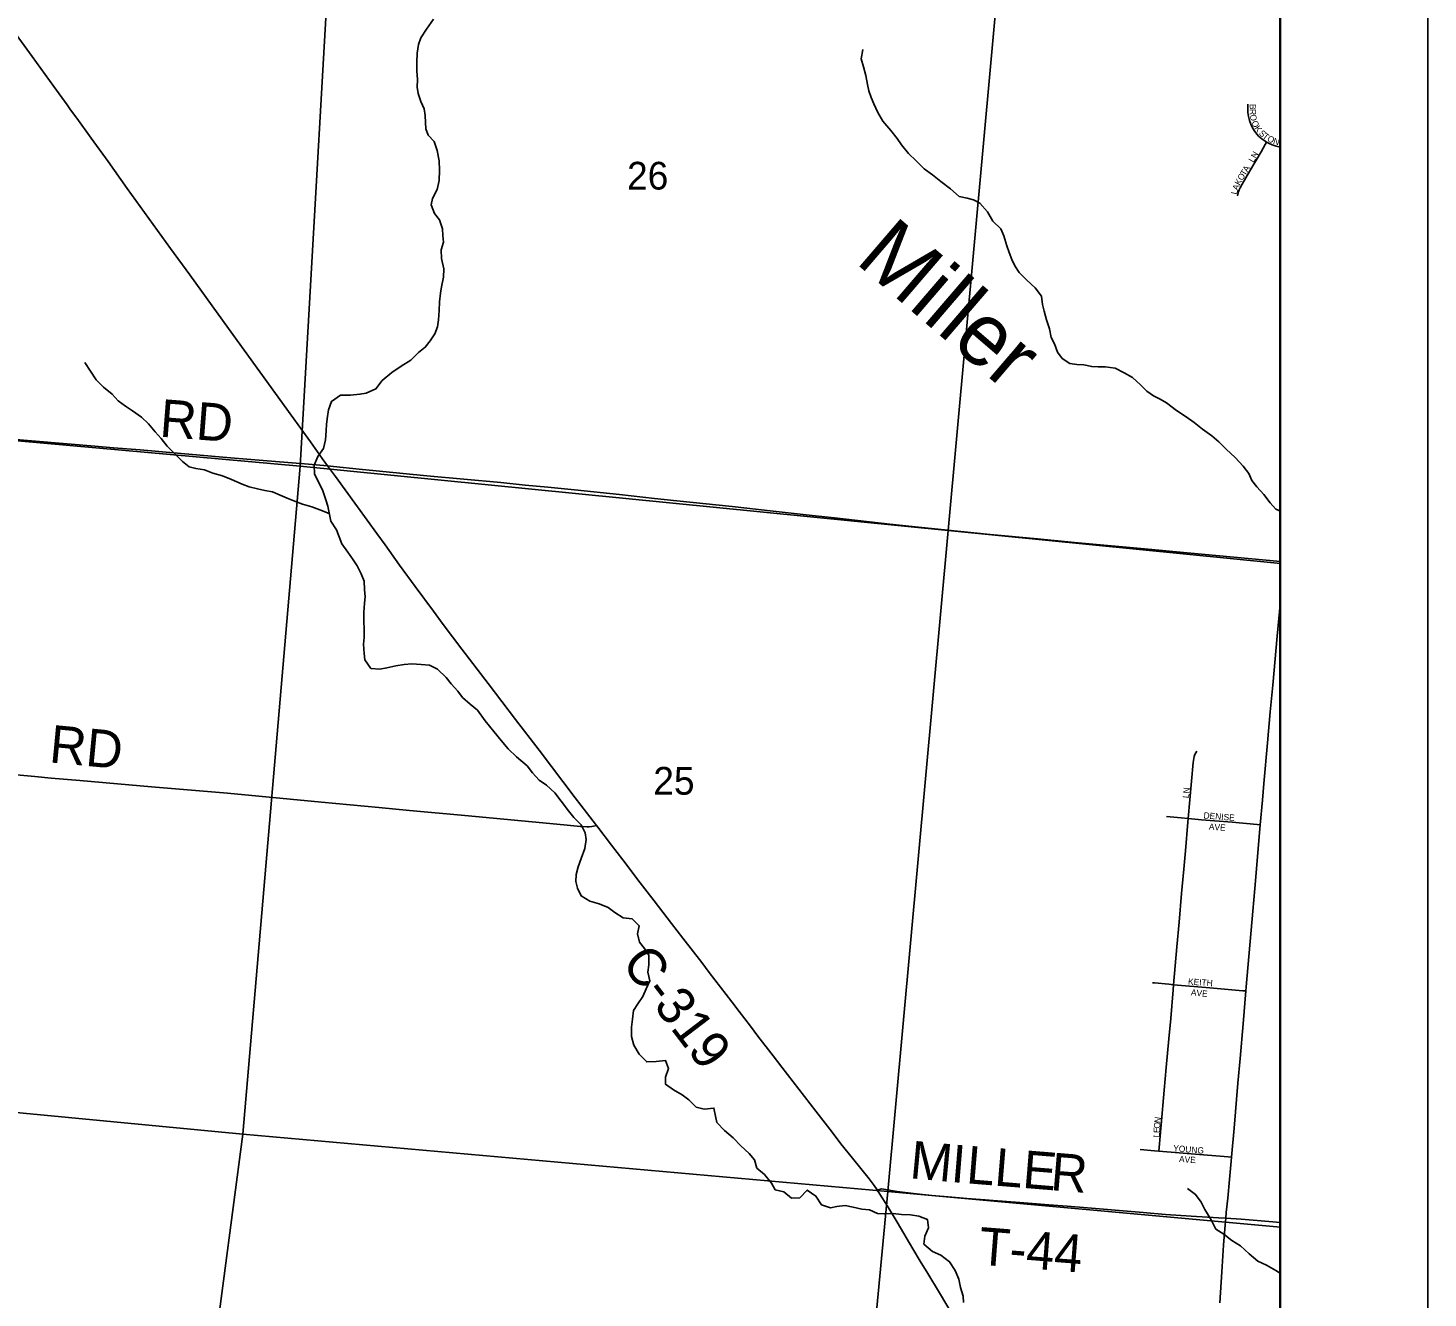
# Model space of a CAD drawing. Extents: x 0 to 680, y 0 to 440.
# Drawn here: x 255.45 to 288.52, y 350.9 to 380.9 of the extents above; entities that cross this region are included whole.
import ezdxf

# ---------------------------------------------------------------- set-up
doc = ezdxf.new("R2010")
doc.units = 0
for name, color, linetype in [('GM_X_Adjacent_County', 7, 'Continuous'), ('GM_X_County', 7, 'Continuous'), ('GM_X_County_Road', 7, 'Continuous'), ('GM_X_County_Road_Text', 7, 'Continuous'), ('GM_X_Minor_River', 7, 'Continuous'), ('GM_X_Minor_River_Text', 7, 'Continuous'), ('GM_X_Section', 7, 'Continuous'), ('GM_X_Section_Text', 7, 'Continuous'), ('GM_X_Township', 7, 'Continuous'), ('GM_X_Township_Road', 7, 'Continuous'), ('GM_X_Township_Road_Text', 7, 'Continuous'), ('GM_X_Township_Subdivision', 7, 'Continuous'), ('GM_X_Township_Subdivision_Text', 7, 'Continuous'), ('SH_Data', 7, 'Continuous'), ('SH_Text', 7, 'Continuous')]:
    doc.layers.add(name, color=color, linetype=linetype)

msp = doc.modelspace()

# ---------------------------------------------------------------- linework, layer by layer
at = {"layer": 'GM_X_Adjacent_County'}
msp.add_lwpolyline([(285.035, 209.752), (285.035, 415.359), (154.698, 415.359)], dxfattribs=at)
at = {"layer": 'GM_X_County'}
msp.add_lwpolyline([(285.035, 209.752), (285.035, 415.359), (154.698, 415.359)], dxfattribs=at)
at = {"layer": 'GM_X_County_Road'}
for points in [[(256.452, 378.972), (256.371, 379.085), (256.058, 379.518), (255.545, 380.227), (254.835, 381.212), (254.38, 381.844), (253.671, 382.83), (253.129, 383.576), (252.618, 384.286), (251.562, 385.742), (251.165, 386.286), (250.907, 386.649), (250.671, 386.958), (250.531, 387.144), (250.516, 387.171), (250.506, 387.2), (250.496, 387.255)], [(262.525, 370.561), (262.402, 370.727), (262.12, 371.123), (261.667, 371.758), (260.925, 372.779), (260.187, 373.805), (259.269, 375.073), (258.818, 375.695), (257.791, 377.113), (257.34, 377.746), (256.94, 378.297), (256.599, 378.77), (256.452, 378.972)], [(268.878, 362.058), (268.642, 362.366), (268.378, 362.715), (267.522, 363.836), (266.965, 364.565), (266.64, 364.99), (266.316, 365.415), (265.7, 366.229), (265.259, 366.809), (265.026, 367.121), (264.592, 367.706), (264.228, 368.212), (263.884, 368.693), (263.689, 368.962), (263.229, 369.589), (262.714, 370.307), (262.525, 370.561)], [(275.505, 353.451), (275.436, 353.552), (275.319, 353.708), (274.922, 354.2), (274.65, 354.542), (274.442, 354.811), (274.057, 355.312), (273.79, 355.659), (273.257, 356.351), (273.048, 356.62), (272.693, 357.083), (272.517, 357.315), (272.252, 357.663), (272.075, 357.894), (271.542, 358.589), (271.365, 358.82), (270.92, 359.397), (270.654, 359.745), (270.238, 360.283), (269.913, 360.708), (269.498, 361.247), (269.234, 361.595), (268.908, 362.019), (268.878, 362.058)], [(280.496, 345.113), (280.311, 345.424), (280.086, 345.799), (279.856, 346.184), (279.636, 346.549), (279.485, 346.799), (278.96, 347.674), (278.787, 347.967), (278.44, 348.552), (278.29, 348.802), (278.019, 349.263), (277.896, 349.472), (277.671, 349.848), (277.302, 350.476), (276.98, 351.021), (276.702, 351.477), (276.527, 351.769), (276.352, 352.061), (275.981, 352.688), (275.754, 353.063), (275.573, 353.351), (275.505, 353.451)]]:
    msp.add_lwpolyline(points, dxfattribs=at)
at = {"layer": 'GM_X_Minor_River'}
for points in [[(263.117, 368.359), (263.006, 368.515), (262.866, 368.712), (262.739, 369.047), (262.605, 369.25), (262.56, 369.447), (262.532, 369.602), (262.486, 369.751), (262.412, 369.966), (262.215, 370.372), (262.211, 370.574), (262.297, 370.775), (262.43, 370.964), (262.474, 371.171), (262.489, 371.385), (262.502, 371.539), (262.523, 371.723), (262.548, 371.878), (262.616, 372.079), (262.832, 372.225), (263.07, 372.228), (263.29, 372.249), (263.439, 372.277), (263.666, 372.376), (263.817, 372.57), (264.046, 372.763), (264.261, 372.91), (264.489, 373.055), (264.67, 373.232), (264.832, 373.36), (264.947, 373.514), (265.062, 373.673), (265.123, 373.838), (265.143, 374.011), (265.158, 374.23), (265.166, 374.432), (265.192, 374.634), (265.218, 374.788), (265.262, 375.014), (265.271, 375.21), (265.214, 375.454), (265.211, 375.662), (265.261, 375.84), (265.251, 376), (265.241, 376.155), (265.166, 376.37), (265.049, 376.52), (264.974, 376.723), (265.006, 376.871), (265.115, 377.083), (265.16, 377.303), (265.169, 377.546), (265.159, 377.766), (265.115, 378.01), (265.046, 378.219), (264.899, 378.37), (264.848, 378.519), (264.838, 378.673), (264.834, 378.834), (264.806, 378.989), (264.731, 379.168), (264.668, 379.353), (264.646, 379.502), (264.648, 379.686), (264.638, 379.894), (264.635, 380.096), (264.643, 380.304), (264.676, 380.512), (264.725, 380.666), (264.859, 380.878), (265.028, 381.108)], [(275.278, 379.568), (275.239, 379.782), (275.182, 379.985), (275.13, 380.17), (275.169, 380.395)], [(285.035, 369.487), (284.924, 369.53), (284.795, 369.68), (284.642, 369.884), (284.478, 370.059), (284.361, 370.208), (284.286, 370.376), (284.157, 370.55), (283.969, 370.754), (283.752, 370.953), (283.582, 371.127), (283.417, 371.265), (283.193, 371.423), (282.998, 371.579), (282.804, 371.712), (282.58, 371.864), (282.344, 372.045), (282.191, 372.136), (282.037, 372.209), (281.878, 372.318), (281.725, 372.474), (281.543, 372.648), (281.342, 372.758), (281.129, 372.867), (280.898, 372.899), (280.731, 372.895), (280.577, 372.903), (280.387, 372.947), (280.221, 372.955), (280.06, 372.975), (279.878, 373.096), (279.766, 373.246), (279.697, 373.437), (279.622, 373.586), (279.577, 373.795), (279.508, 374.009), (279.451, 374.212), (279.412, 374.373), (279.39, 374.563), (279.244, 374.761), (279.044, 374.948), (278.862, 375.122), (278.763, 375.284), (278.687, 375.433), (278.624, 375.6), (278.572, 375.756), (278.504, 375.994), (278.429, 376.155), (278.241, 376.336), (278.118, 376.557), (277.937, 376.767), (277.783, 376.846), (277.635, 376.878), (277.445, 376.922), (277.239, 377.102), (277.015, 377.277), (276.815, 377.434), (276.621, 377.573), (276.427, 377.76), (276.245, 377.94), (276.087, 378.138), (275.981, 378.288), (275.829, 378.48), (275.642, 378.702), (275.525, 378.905), (275.427, 379.114), (275.369, 379.264), (275.311, 379.419), (275.278, 379.568)], [(262.564, 369.431), (262.341, 369.521), (262.151, 369.588), (261.932, 369.65), (261.767, 369.712), (261.571, 369.791), (261.406, 369.864), (261.228, 369.944), (261.044, 369.976), (260.872, 370.013), (260.671, 370.063), (260.511, 370.125), (260.257, 370.235), (260.044, 370.32), (259.819, 370.388), (259.617, 370.462), (259.416, 370.494), (259.256, 370.537), (259.097, 370.658), (258.938, 370.821), (258.738, 371.019), (258.592, 371.205), (258.457, 371.361), (258.299, 371.553), (258.128, 371.71), (257.916, 371.861), (257.751, 371.97), (257.58, 372.096), (257.439, 372.253), (257.233, 372.415), (257.057, 372.59), (256.789, 372.997)], [(273.682, 353.263), (273.485, 353.254), (273.303, 353.404), (273.101, 353.448), (273.014, 353.61), (272.85, 353.814), (272.668, 353.965), (272.611, 354.161), (272.482, 354.312), (272.288, 354.492), (272.106, 354.684), (271.9, 354.853), (271.724, 355.04), (271.69, 355.189), (271.651, 355.385), (271.424, 355.358), (271.235, 355.402), (271.058, 355.576), (270.899, 355.697), (270.699, 355.812), (270.51, 355.945), (270.506, 356.112), (270.58, 356.319), (270.505, 356.51), (270.285, 356.483), (270.065, 356.474), (269.889, 356.654), (269.76, 356.87), (269.704, 357.078), (269.706, 357.292), (269.732, 357.488), (269.753, 357.69), (269.856, 357.843), (269.971, 358.02), (270.05, 358.204), (270.136, 358.393), (270.091, 358.595), (270.117, 358.768), (270.114, 358.999), (270.015, 359.155), (269.897, 359.305), (269.846, 359.502), (269.89, 359.691), (269.72, 359.854), (269.512, 359.88), (269.311, 360.007), (269.152, 360.122), (268.939, 360.208), (268.72, 360.27), (268.52, 360.397), (268.427, 360.576), (268.393, 360.737), (268.395, 360.904), (268.445, 361.081), (268.513, 361.277), (268.599, 361.513), (268.637, 361.727), (268.609, 361.888), (268.516, 362.073), (268.346, 362.247), (268.217, 362.403), (268.042, 362.631), (267.895, 362.835), (267.695, 363.01), (267.524, 363.131), (267.366, 363.305), (267.237, 363.473), (266.99, 363.684), (266.79, 363.87), (266.626, 364.068), (266.451, 364.278), (266.246, 364.536), (266.064, 364.782), (265.894, 364.927), (265.717, 365.083), (265.6, 365.233), (265.442, 365.407), (265.331, 365.557), (265.125, 365.756), (264.93, 365.847), (264.734, 365.867), (264.52, 365.876), (264.335, 365.86), (264.139, 365.833), (263.924, 365.782), (263.757, 365.754), (263.549, 365.768), (263.409, 365.972), (263.393, 366.121), (263.378, 366.347), (263.392, 366.501), (263.389, 366.709), (263.379, 366.876), (263.381, 367.096), (263.402, 367.309), (263.41, 367.464), (263.4, 367.636), (263.39, 367.832), (263.321, 368.006), (263.222, 368.197), (263.117, 368.359)], [(277.546, 350.793), (277.542, 350.941), (277.479, 351.144), (277.434, 351.341), (277.347, 351.544), (277.219, 351.754), (277.013, 351.905), (276.812, 351.996), (276.612, 352.171), (276.632, 352.355), (276.723, 352.556), (276.696, 352.752), (276.495, 352.826), (276.293, 352.858), (276.085, 352.867), (275.889, 352.893), (275.675, 352.883), (275.52, 352.891), (275.325, 352.982), (275.147, 352.996), (274.94, 353.046), (274.756, 353.078), (274.559, 353.057), (274.404, 353.029), (274.197, 353.097), (274.063, 353.306), (273.857, 353.445), (273.682, 353.263)], [(285.035, 351.477), (284.922, 351.545), (284.704, 351.672), (284.503, 351.77), (284.297, 351.938), (284.091, 352.125), (283.89, 352.252), (283.696, 352.403), (283.507, 352.524), (283.397, 352.74), (283.251, 352.985), (283.158, 353.164), (283.03, 353.344), (282.841, 353.483)]]:
    msp.add_lwpolyline(points, dxfattribs=at)
at = {"layer": 'GM_X_Section'}
for points in [[(248.075, 387.46), (262.767, 386.107), (261.88, 370.548), (246.691, 371.915)], [(262.767, 386.107), (278.599, 384.575), (277.185, 369.031), (261.88, 370.548)], [(285.035, 368.251), (285.035, 383.915), (278.599, 384.575), (277.185, 369.031)], [(246.691, 371.915), (261.88, 370.548), (260.527, 354.766), (245.115, 356.243)], [(261.88, 370.548), (277.185, 369.031), (275.758, 353.416), (260.527, 354.766)], [(285.035, 352.57), (285.035, 368.251), (277.185, 369.031), (275.758, 353.416)], [(245.115, 356.243), (260.527, 354.766), (258.466, 339.173), (243.775, 340.544)], [(260.527, 354.766), (275.758, 353.416), (274.289, 337.825), (258.466, 339.173)], [(285.035, 336.872), (285.035, 352.57), (275.758, 353.416), (274.289, 337.825)]]:
    msp.add_lwpolyline(points, close=True, dxfattribs=at)
at = {"layer": 'GM_X_Township'}
msp.add_lwpolyline([(243.787, 340.531), (258.485, 339.173), (267.813, 338.347), (274.304, 337.773), (285.035, 336.894), (285.035, 415.359)], dxfattribs=at)
at = {"layer": 'GM_X_Township_Road'}
for points in [[(246.687, 371.891), (246.791, 371.883), (246.888, 371.875), (247.422, 371.828), (248.004, 371.785), (250.819, 371.549), (251.353, 371.505), (252.372, 371.42), (252.905, 371.372), (253.536, 371.318), (254.215, 371.259), (257.029, 371.021), (257.466, 370.984), (258.096, 370.932), (259.067, 370.847), (260.231, 370.748), (261.008, 370.685), (262.075, 370.596), (262.525, 370.561)], [(262.525, 370.561), (262.667, 370.541), (263.273, 370.479), (264.871, 370.325), (266.615, 370.16), (267.196, 370.103), (267.728, 370.051), (268.358, 369.987), (269.423, 369.877), (270.245, 369.785), (270.777, 369.728), (272.084, 369.594), (273.051, 369.484), (273.97, 369.386), (274.502, 369.326), (275.808, 369.179), (276.485, 369.109), (278.18, 368.935), (279.294, 368.831), (280.166, 368.749), (281.91, 368.586), (282.829, 368.505), (285.035, 368.299)], [(284.558, 362.077), (284.609, 362.659), (284.643, 363.05), (284.731, 364.016), (284.795, 364.743), (284.854, 365.372), (284.96, 366.535), (285.035, 367.365)], [(254.641, 363.306), (255.609, 363.219), (255.996, 363.182), (256.673, 363.125), (257.835, 363.024), (258.367, 362.975), (260.158, 362.821), (262.383, 362.609), (263.738, 362.482), (264.463, 362.413), (265.77, 362.295), (267.362, 362.145), (268.104, 362.072), (268.502, 362.037), (268.505, 362.037)], [(268.505, 362.037), (268.647, 362.027), (268.704, 362.027), (268.769, 362.037), (268.846, 362.052), (268.878, 362.058)], [(284.215, 358.15), (284.223, 358.249), (284.383, 360.037), (284.428, 360.575), (284.558, 362.077)], [(283.876, 354.227), (283.939, 354.905), (284.03, 355.971), (284.084, 356.552), (284.151, 357.377), (284.215, 358.15)], [(283.742, 352.781), (283.754, 352.919), (283.79, 353.257), (283.828, 353.694), (283.867, 354.129), (283.876, 354.227)], [(275.505, 353.451), (275.56, 353.462), (275.611, 353.472), (275.655, 353.47), (275.981, 353.415), (276.366, 353.367), (276.801, 353.319), (277.188, 353.284), (277.623, 353.247), (278.059, 353.212), (278.252, 353.196), (278.882, 353.15), (279.56, 353.097), (279.996, 353.063), (280.385, 353.032), (281.788, 352.913), (282.32, 352.871), (282.925, 352.829), (283.571, 352.793), (283.742, 352.781)], [(283.602, 350.784), (283.65, 351.512), (283.691, 352.144), (283.728, 352.628), (283.742, 352.781)], [(283.742, 352.781), (284.106, 352.757), (284.487, 352.728), (285.035, 352.683)]]:
    msp.add_lwpolyline(points, dxfattribs=at)
at = {"layer": 'GM_X_Township_Subdivision'}
for points in [[(284.268, 379.102), (284.264, 379.005), (284.265, 378.909), (284.277, 378.813), (284.3, 378.719), (284.333, 378.629), (284.375, 378.542), (284.426, 378.46), (284.455, 378.422), (284.52, 378.35), (284.592, 378.286), (284.67, 378.228), (284.705, 378.207)], [(284.018, 376.939), (284.045, 377.035), (284.062, 377.082), (284.082, 377.127), (284.128, 377.215), (284.303, 377.512), (284.579, 377.977), (284.673, 378.149), (284.705, 378.207)], [(284.705, 378.207), (284.753, 378.179), (284.841, 378.139), (284.932, 378.109), (285.026, 378.088), (285.035, 378.086)], [(282.858, 362.227), (282.97, 363.546), (282.985, 363.641), (282.997, 363.688), (283.014, 363.734), (283.057, 363.82)], [(282.346, 362.273), (282.686, 362.244), (282.858, 362.227)], [(282.508, 358.299), (282.588, 359.192), (282.642, 359.773), (282.701, 360.45), (282.756, 361.03), (282.793, 361.465), (282.85, 362.142), (282.858, 362.227)], [(282.858, 362.227), (283.17, 362.197), (283.898, 362.136), (284.481, 362.084), (284.558, 362.077)], [(282.013, 358.343), (282.061, 358.339), (282.4, 358.308), (282.508, 358.299)], [(282.164, 354.364), (282.172, 354.453), (282.216, 354.985), (282.286, 355.807), (282.336, 356.339), (282.395, 357.016), (282.442, 357.499), (282.497, 358.177), (282.508, 358.299)], [(282.508, 358.299), (283.369, 358.226), (284.144, 358.156), (284.215, 358.15)], [(281.724, 354.407), (282.06, 354.372), (282.164, 354.364)], [(282.164, 354.364), (283.219, 354.276), (283.702, 354.236), (283.799, 354.232), (283.876, 354.227)]]:
    msp.add_lwpolyline(points, dxfattribs=at)
at = {"layer": 'SH_Data'}
for p, q in [((288.52, 418.859), (288.52, 173.859)), ((285.02, 415.359), (285.02, 177.359))]:
    msp.add_line(p, q, dxfattribs=at)
at = {"layer": 'SH_Text'}
for points in [[(47.02, 415.359), (285.02, 415.359), (285.02, 177.359), (47.02, 177.359)], [(285.019, 415.359), (47.02, 415.359), (47.02, 177.359), (285.019, 177.359)]]:
    msp.add_lwpolyline(points, close=True, dxfattribs=at)

# ---------------------------------------------------------------- texts
at = {"layer": 'GM_X_County_Road_Text'}
msp.add_text('C-319', height=0.8894, rotation=307.3054, dxfattribs=at).set_placement((269.446, 358.801))
at = {"layer": 'GM_X_Minor_River_Text'}
msp.add_text('Miller', height=1.4821, rotation=319.3471, dxfattribs=at).set_placement((274.966, 375.373))
at = {"layer": 'GM_X_Section_Text'}
for s, p in [('26', (269.6, 377.085)), ('25', (270.22, 362.788))]:
    msp.add_text(s, height=0.6552, rotation=0, dxfattribs=at).set_placement(p)
at = {"layer": 'GM_X_Township_Road_Text'}
for s, height, rotation, p in [('RD', 0.8894, 355.5636, (258.542, 371.249)), ('RD', 0.8894, 354.5825, (255.933, 363.553)), ('M', 0.889, 354.67, (276.259, 353.729)), ('I', 0.889, 355.3686, (277.232, 353.638)), ('L', 0.889, 355.3535, (277.596, 353.609)), ('L', 0.889, 355.3535, (278.259, 353.555)), ('E', 0.889, 355.3535, (278.922, 353.501)), ('R', 0.889, 355.3564, (279.585, 353.447)), ('T-44', 0.8894, 355.5221, (277.886, 351.687))]:
    msp.add_text(s, height=height, rotation=rotation, dxfattribs=at).set_placement(p)
at = {"layer": 'GM_X_Township_Subdivision_Text'}
for s, height, rotation, p in [('B', 0.148, 270.1943, (284.309, 379.106)), ('R', 0.148, 270.2077, (284.31, 378.988)), ('O', 0.148, 277.7821, (284.312, 378.85)), ('O', 0.148, 295.8499, (284.344, 378.672)), ('K', 0.148, 304.5208, (284.413, 378.533)), ('S', 0.148, 318.3974, (284.513, 378.396)), ('T', 0.148, 321.8678, (284.599, 378.321)), ('O', 0.148, 332.8254, (284.707, 378.24)), ('N', 0.148, 343.496, (284.851, 378.169)), ('LN', 0.1482, 60.6435, (284.401, 377.711)), ('K', 0.148, 60.9518, (284.072, 377.171)), ('O', 0.148, 59.0325, (284.135, 377.284)), ('T', 0.148, 58.7738, (284.202, 377.396)), ('A', 0.148, 58.7819, (284.256, 377.485)), ('L', 0.148, 77.1897, (284.006, 376.958)), ('A', 0.148, 68.7993, (284.027, 377.054)), ('LN', 0.1482, 83.9946, (282.871, 362.699)), ('DENISE', 0.1482, 355.3357, (283.214, 362.228)), ('AVE', 0.1482, 356.0569, (283.34, 361.961)), ('KEITH', 0.1482, 355.9166, (282.848, 358.302)), ('AVE', 0.1482, 354.0969, (282.914, 358.048)), ('E', 0.148, 87.4036, (282.184, 354.792)), ('O', 0.148, 85.6901, (282.189, 354.895)), ('N', 0.148, 82.284, (282.198, 355.023)), ('L', 0.148, 87.4309, (282.179, 354.688)), ('YOUNG', 0.1482, 355.4245, (282.497, 354.363)), ('AVE', 0.1482, 356.0494, (282.635, 354.108))]:
    msp.add_text(s, height=height, rotation=rotation, dxfattribs=at).set_placement(p)

doc.saveas('drawing.dxf')
